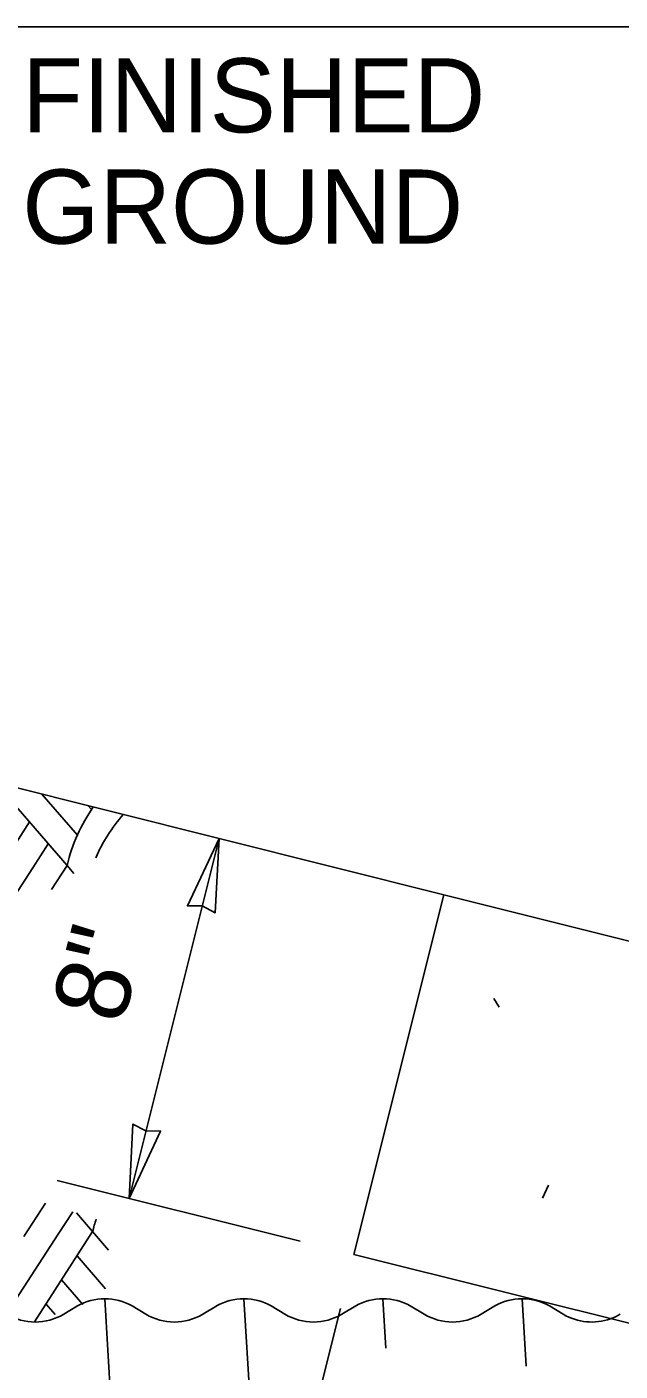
# Model space of a CAD drawing. Extents: x 99862 to 103151, y 100000 to 102076.
# Drawn here: x 100809.3 to 100937.3, y 101785.5 to 102075.5 of the extents above; entities that cross this region are included whole.
import ezdxf

# ---------------------------------------------------------------- set-up
doc = ezdxf.new("R2010")
doc.units = 0
for name, color, linetype in [('Level 1', 7, 'Continuous'), ('Level 13', 7, 'Continuous'), ('Level 15', 7, 'Continuous'), ('Level 17', 7, 'Continuous'), ('Level 20', 7, 'Continuous')]:
    doc.layers.add(name, color=color, linetype=linetype)

msp = doc.modelspace()

# ---------------------------------------------------------------- linework, layer by layer
at = {"layer": 'Level 1'}
for p, q in [((100802.51, 101912.5), (100817.98, 101894.63)), ((100812.53, 101910), (100820.2, 101901.13)), ((100822.55, 101907.5), (100823.27, 101906.67)), ((100803.16, 101893.59), (100809.88, 101903.99)), ((100810.57, 101894.11), (100813.93, 101899.31)), ((100814.62, 101889.43), (100817.98, 101894.63)), ((100817.98, 101894.63), (100819.46, 101892.91)), ((100801.43, 101879.97), (100810.57, 101894.11)), ((100808.69, 101814.59), (100813.33, 101821.77)), ((100816.09, 101815.11), (100819.21, 101819.93)), ((100819.99, 101819.69), (100823.5, 101815.63)), ((100806.96, 101800.97), (100816.09, 101815.11)), ((100810.94, 101796.19), (100823.5, 101815.63)), ((100823.5, 101815.63), (100826.95, 101811.64)), ((100820.14, 101810.43), (100826.29, 101803.32)), ((100816.78, 101805.23), (100821.41, 101799.89)), ((100813.43, 101800.04), (100815.4, 101797.75)), ((100817.26, 101797.81), (100820.25, 101799.59)), ((100841.12, 101551.13), (100826.12, 101801.13)), ((100832, 101799.59), (100834.98, 101797.81)), ((100832, 101799.59), (100834.98, 101797.81)), ((100847.26, 101797.81), (100850.25, 101799.59)), ((100847.26, 101797.81), (100850.25, 101799.59)), ((100850.25, 101799.59), (100847.26, 101797.81)), ((100847.26, 101797.81), (100850.25, 101799.59)), ((100871.12, 101551.13), (100856.12, 101801.13)), ((100864.98, 101797.81), (100862, 101799.59)), ((100880.25, 101799.59), (100877.26, 101797.81)), ((100886.76, 101790.46), (100886.12, 101801.13)), ((100892, 101799.59), (100894.98, 101797.81)), ((100907.26, 101797.81), (100910.25, 101799.59)), ((100916.99, 101786.6), (100916.12, 101801.13)), ((100924.98, 101797.81), (100922, 101799.59)), ((100834.98, 101797.81), (100834.98, 101797.81)), ((100847.26, 101797.81), (100847.26, 101797.81)), ((100924.98, 101797.81), (100924.98, 101797.81)), ((100937.26, 101797.81), (100937.26, 101797.81))]:
    msp.add_line(p, q, dxfattribs=at)
msp.add_lwpolyline([(99862, 99999.5), (103151, 99999.5), (103151, 102075.5), (99862, 102075.5)], close=True, dxfattribs=at)
for centre, radius, start, end in [((100854.49, 101885.77), 37.58, 145.1795, 166.3566), ((100858.54, 101881.09), 37.58, 139.2501, 156.1422), ((100860.02, 101806.76), 37.58, 162.0511, 166.3566), ((100826.12, 101789.13), 12, 90, 119.3129), ((100826.12, 101789.13), 12, 60.6871, 90), ((100826.12, 101789.13), 12, 60.6871, 90), ((100856.12, 101789.13), 12, 90, 119.3129), ((100856.12, 101789.13), 12, 90, 119.3129), ((100856.12, 101789.13), 12, 90, 119.3129), ((100856.12, 101789.13), 12, 90, 119.3129), ((100856.12, 101789.13), 12, 60.6871, 90), ((100886.12, 101789.13), 12, 90, 119.3129), ((100886.12, 101789.13), 12, 60.6871, 90), ((100916.12, 101789.13), 12, 90, 119.3129), ((100916.12, 101789.13), 12, 60.6871, 90), ((100811.12, 101808.13), 12, 239.2401, 300.7599), ((100841.12, 101808.13), 12, 239.2401, 300.7599), ((100841.12, 101808.13), 12, 239.2401, 300.7599), ((100841.12, 101808.13), 12, 239.2401, 300.7599), ((100841.12, 101808.13), 12, 239.2401, 300.7599), ((100871.12, 101808.13), 12, 239.2401, 300.7599), ((100901.12, 101808.13), 12, 239.2401, 300.7599), ((100931.12, 101808.13), 12, 239.2401, 289.8739), ((100931.12, 101808.13), 12, 289.9289, 300.7599), ((100931.12, 101808.13), 12, 289.9289, 300.7599)]:
    msp.add_arc(centre, radius, start, end, dxfattribs=at)
at = {"layer": 'Level 13'}
for p, q in [((100879.86, 101810.68), (100899.26, 101888.29)), ((100899.26, 101888.29), (102226.12, 101556.57)), ((102146.12, 101494.11), (100879.86, 101810.68))]:
    msp.add_line(p, q, dxfattribs=at)
at = {"layer": 'Level 15'}
for p, q in [((100590.48, 101965.49), (100899.26, 101888.29)), ((100831.35, 101822.8), (100850.76, 101900.42)), ((100868.22, 101813.59), (100815.84, 101826.68)), ((100876.95, 101799.04), (100864.55, 101749.42))]:
    msp.add_line(p, q, dxfattribs=at)
for points in [[(100850.76, 101900.42), (100843.95, 101885.91), (100847.12, 101885.87), (100849.94, 101884.41)], [(100831.35, 101822.8), (100838.16, 101837.31), (100834.99, 101837.35), (100832.18, 101838.81)]]:
    msp.add_lwpolyline(points, close=True, dxfattribs=at)
at = {"layer": 'Level 17'}
for p, q in [((100910.02, 101865.9), (100911.2, 101864.03)), ((100920.55, 101822.87), (100921.8, 101825.63))]:
    msp.add_line(p, q, dxfattribs=at)

# ---------------------------------------------------------------- texts
at = {"layer": 'Level 20'}
for s, p in [('FINISHED', (100808.32, 102052.74)), ('GROUND', (100808.32, 102028.74))]:
    msp.add_text(s, height=16, dxfattribs=at).set_placement(p)
msp.add_text('8"', height=16, rotation=75.2084, dxfattribs=at).set_placement((100829.9, 101859.95))

doc.saveas('drawing.dxf')
